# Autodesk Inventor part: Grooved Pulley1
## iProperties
Created: 2011-05
Part Number: Grooved Pulley1
Material: Steel
Document SubType Name: Modeling
Designer: 904Chiaki
Density: 1 g/cm^3
CustomPartVersion: 1
Author: 904Chiaki
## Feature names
1. Body [Revolution]
2. Groove [Revolution]
3. Fillet External
4. Fillet Internal
5. Groove Pattern [Rectangular Pattern]
6. Extrusion1
7. Extrusion2
8. Mirror1
9. Chamfer1
10. Chamfer2
11. Extrusion3
12. Extrusion4
13. Fillet3
14. Fillet4
15. Fillet5
16. Fillet6
17. Fillet7
18. Chamfer3
